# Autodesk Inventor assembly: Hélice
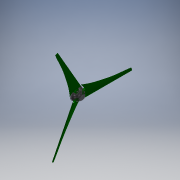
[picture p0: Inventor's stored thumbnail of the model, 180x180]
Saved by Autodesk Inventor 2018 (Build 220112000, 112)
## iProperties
Created: 2014-09
Part Number: Hélice
Document SubType Name: Assembly
Designer: papa
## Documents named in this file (7)
- H:\Consmec\1si\TP\Cycle1\01-02-TP02-Eolienne\01-02-02- Dossier Technique\01-02-02-03-Maquette numerique\Helice\Hélice.iam
- H:\Consmec\1si\TP\Cycle1\01-02-TP02-Eolienne\01-02-02- Dossier Technique\01-02-02-03-Maquette numerique\Helice\15-Moyeu.ipt
- H:\Consmec\1si\TP\Cycle1\01-02-TP02-Eolienne\01-02-02- Dossier Technique\01-02-02-03-Maquette numerique\Helice\16-Pâle.ipt
- H:\Consmec\1si\TP\Cycle1\01-02-TP02-Eolienne\01-02-02- Dossier Technique\01-02-02-03-Maquette numerique\Helice\17-Nez.ipt
- C:\Users\TJ\Documents\Inventor\Content Center Files\R2018\fr-FR\NF E 25-125\NF E 25-125 - M6 x 30.ipt
- H:\Consmec\1si\TP\Cycle1\01-02-TP02-Eolienne\01-02-02- Dossier Technique\01-02-02-03-Maquette numerique\Helice\23-Ecrou H FR M6, DIN 985.ipt
- H:\Consmec\1si\TP\Cycle1\01-02-TP02-Eolienne\01-02-02- Dossier Technique\01-02-02-03-Maquette numerique\Helice\22-Rondelle-ISO 7089 - 6 - 140 HV.ipt
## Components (14 placed, 6 different names)
1. moyeu:1 — Logement:1, Angle:1, Logement:2, Angle:2, Logement:3, Angle:3, Logement:5, Logement:6, Logement:7, Angle:4, Angle:5, Angle:6, Affleurement:3, Placage:2
2. pâle:1 — Logement:1, Angle:1
3. pâle:2 — Logement:3, Angle:3
4. pâle:3 — Logement:2, Angle:2, Placage:1
5. nez:1 — Placage:1, Affleurement:3, Placage:2
6. NF E 25-125 M6 x 30:1 — Logement:13
7. 23-Ecrou H FR M6, DIN 985:1 — Logement:7, Angle:4
8. 23-Ecrou H FR M6, DIN 985:2 — Logement:6, Angle:6
9. 23-Ecrou H FR M6, DIN 985:3 — Logement:5, Angle:5
10. NF E 25-125 M6 x 30:2 — Logement:12
11. NF E 25-125 M6 x 30:3 — Logement:11
12. ISO 7089 6:1 — Logement:12
13. ISO 7089 6:2 — Logement:13
14. ISO 7089 6:3 — Logement:11
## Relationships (18: Insert 9, Angle 6, Mate 2, Flush 1)
- Logement:1 [Insert]: moyeu:1 ↔ pâle:1
- Angle:1: moyeu:1 ↔ pâle:1
- Logement:2 [Insert]: moyeu:1 ↔ pâle:3
- Angle:2: moyeu:1 ↔ pâle:3
- Logement:3 [Insert]: moyeu:1 ↔ pâle:2
- Angle:3: moyeu:1 ↔ pâle:2
- Logement:5 [Insert]: moyeu:1 ↔ 23-Ecrou H FR M6, DIN 985:3
- Logement:6 [Insert]: moyeu:1 ↔ 23-Ecrou H FR M6, DIN 985:2
- Logement:7 [Insert]: moyeu:1 ↔ 23-Ecrou H FR M6, DIN 985:1
- Angle:4: moyeu:1 ↔ 23-Ecrou H FR M6, DIN 985:1
- Angle:5: moyeu:1 ↔ 23-Ecrou H FR M6, DIN 985:3
- Angle:6: moyeu:1 ↔ 23-Ecrou H FR M6, DIN 985:2
- Logement:11 [Insert]: NF E 25-125 M6 x 30:3 ↔ ISO 7089 6:3
- Logement:12 [Insert]: NF E 25-125 M6 x 30:2 ↔ ISO 7089 6:1
- Logement:13 [Insert]: NF E 25-125 M6 x 30:1 ↔ ISO 7089 6:2
- Placage:1 [Mate]: pâle:3 ↔ nez:1
- Affleurement:3 [Flush]: moyeu:1 ↔ nez:1
- Placage:2 [Mate]: moyeu:1 ↔ nez:1
